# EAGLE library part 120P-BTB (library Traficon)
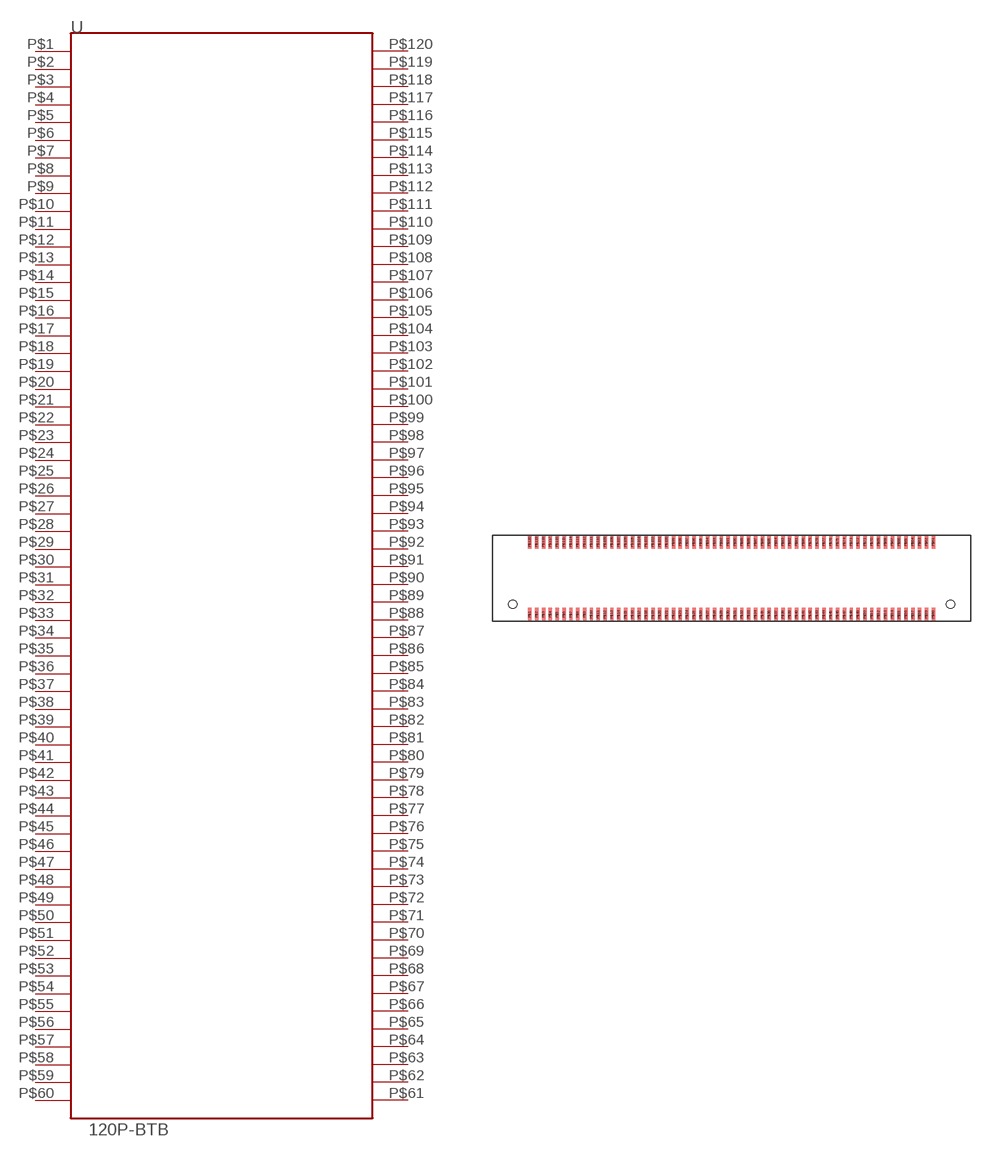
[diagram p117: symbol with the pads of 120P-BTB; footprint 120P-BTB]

Designator prefix -

## 120P-BTB  [120P-BTB]
P$1  1
P$2  3
P$3  5
P$4  7
P$5  9
P$6  11
P$7  13
P$8  15
P$9  17
P$10  19
P$11  21
P$12  23
P$13  25
P$14  27
P$15  29
P$16  31
P$17  33
P$18  35
P$19  37
P$20  39
P$21  41
P$22  43
P$23  45
P$24  47
P$25  49
P$26  51
P$27  53
P$28  55
P$29  57
P$30  59
P$31  61
P$32  63
P$33  65
P$34  67
P$35  69
P$36  71
P$37  73
P$38  75
P$39  77
P$40  79
P$41  81
P$42  83
P$43  85
P$44  87
P$45  89
P$46  91
P$47  93
P$48  95
P$49  97
P$50  99
P$51  101
P$52  103
P$53  105
P$54  107
P$55  109
P$56  111
P$57  113
P$58  115
P$59  117
P$60  119
P$61  120
P$62  118
P$63  116
P$64  114
P$65  112
P$66  110
P$67  108
P$68  106
P$69  104
P$70  102
P$71  100
P$72  98
P$73  96
P$74  94
P$75  92
P$76  90
P$77  88
P$78  86
P$79  84
P$80  82
P$81  80
P$82  78
P$83  76
P$84  74
P$85  72
P$86  70
P$87  68
P$88  66
P$89  64
P$90  62
P$91  60
P$92  58
P$93  56
P$94  54
P$95  52
P$96  50
P$97  48
P$98  46
P$99  44
P$100  42
P$101  40
P$102  38
P$103  36
P$104  34
P$105  32
P$106  30
P$107  28
P$108  26
P$109  24
P$110  22
P$111  20
P$112  18
P$113  16
P$114  14
P$115  12
P$116  10
P$117  8
P$118  6
P$119  4
P$120  2

## Footprint 120P-BTB (pad centres in mm)
smd 0.25 x 1: P$1 0,0; P$2 0.5,0; P$3 1,0; P$4 1.5,0; P$5 2,0; P$6 2.5,0; P$7 3,0; P$8 3.5,0; P$9 4,0; P$10 4.5,0; P$11 5,0; P$12 5.5,0; P$13 6,0; P$14 6.5,0; P$15 7,0; P$16 7.5,0; P$17 8,0; P$18 8.5,0; P$19 9,0; P$20 9.5,0; P$21 10,0; P$22 10.5,0; P$23 11,0; P$24 11.5,0; P$25 12,0; P$26 12.5,0; P$27 13,0; P$28 13.5,0; P$29 14,0; P$30 14.5,0; P$31 15,0; P$32 15.5,0; P$33 16,0; P$34 16.5,0; P$35 17,0; P$36 17.5,0; P$37 18,0; P$38 18.5,0; P$39 19,0; P$40 19.5,0; P$41 20,0; P$42 20.5,0; P$43 21,0; P$44 21.5,0; P$45 22,0; P$46 22.5,0; P$47 23,0; P$48 23.5,0; P$49 24,0; P$50 24.5,0; P$51 25,0; P$52 25.5,0; P$53 26,0; P$54 26.5,0; P$55 27,0; P$56 27.5,0; P$57 28,0; P$58 28.5,0; P$59 29,0; P$60 29.5,0; P$61 29.5,5.3; P$62 29,5.3; P$63 28.5,5.3; P$64 28,5.3; P$65 27.5,5.3; P$66 27,5.3; P$67 26.5,5.3; P$68 26,5.3; P$69 25.5,5.3; P$70 25,5.3; P$71 24.5,5.3; P$72 24,5.3; P$73 23.5,5.3; P$74 23,5.3; P$75 22.5,5.3; P$76 22,5.3; P$77 21.5,5.3; P$78 21,5.3; P$79 20.5,5.3; P$80 20,5.3; P$81 19.5,5.3; P$82 19,5.3; P$83 18.5,5.3; P$84 18,5.3; P$85 17.5,5.3; P$86 17,5.3; P$87 16.5,5.3; P$88 16,5.3; P$89 15.5,5.3; P$90 15,5.3; P$91 14.5,5.3; P$92 14,5.3; P$93 13.5,5.3; P$94 13,5.3; P$95 12.5,5.3; P$96 12,5.3; P$97 11.5,5.3; P$98 11,5.3; P$99 10.5,5.3; P$100 10,5.3; P$101 9.5,5.3; P$102 9,5.3; P$103 8.5,5.3; P$104 8,5.3; P$105 7.5,5.3; P$106 7,5.3; P$107 6.5,5.3; P$108 6,5.3; P$109 5.5,5.3; P$110 5,5.3; P$111 4.5,5.3; P$112 4,5.3; P$113 3.5,5.3; P$114 3,5.3; P$115 2.5,5.3; P$116 2,5.3; P$117 1.5,5.3; P$118 1,5.3; P$119 0.5,5.3; P$120 0,5.3
hole 0.6 at -1.25,0.75
hole 0.6 at -1.25,0.75
hole 0.6 at 30.75,0.75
